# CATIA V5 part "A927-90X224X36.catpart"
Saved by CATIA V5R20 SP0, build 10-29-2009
Part number: A927-90X224X36
Source: Unknown
Property "A": "50.000"
Property "ARTICLENO": "A927-90X224X36"
Property "BOMINFO": "A927-90X224X36"
Property "CODE": "A927-90X224X36"
Property "CREATOR": "CADENAS GmbH"
Property "D": "18.000"
Property "D1": "26.000"
Property "F": "28.000"
Property "FORM": "A"
Property "L": "224.000"
Property "L1": "100.000"
Property "L2": "20.000"
Property "L3": "50.000"
Property "LINA": "A927-90X224X36"
Property "NB": "A927-90X224X36"
Property "NBSYN": "$CODE."
Property "NN": "A927"
Property "NT": "VDI 3387 Removable Die Heels, steel and self-lubricating"
Property "R": "25.000"
Property "S": "36.000"
Property "SUPPLIER": "CF"
Property "T": "21.000"
Property "W": "90.000"
Bounding box of the stored display mesh (mm): x -45 to 45, y 0 to 224, z -36 to 0
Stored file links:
  C:\Users\borellobunino\Desktop\3D X SITO CF\A927\GSB_OILLESS_G2290509022436\CATIAV5\A927-90X224X36.catpart
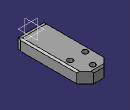
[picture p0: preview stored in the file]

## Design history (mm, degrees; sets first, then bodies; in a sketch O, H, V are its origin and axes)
Body1 "Geometry.1" (main body)
  Solid1 "A927-90X224X36.catpart": solid without history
